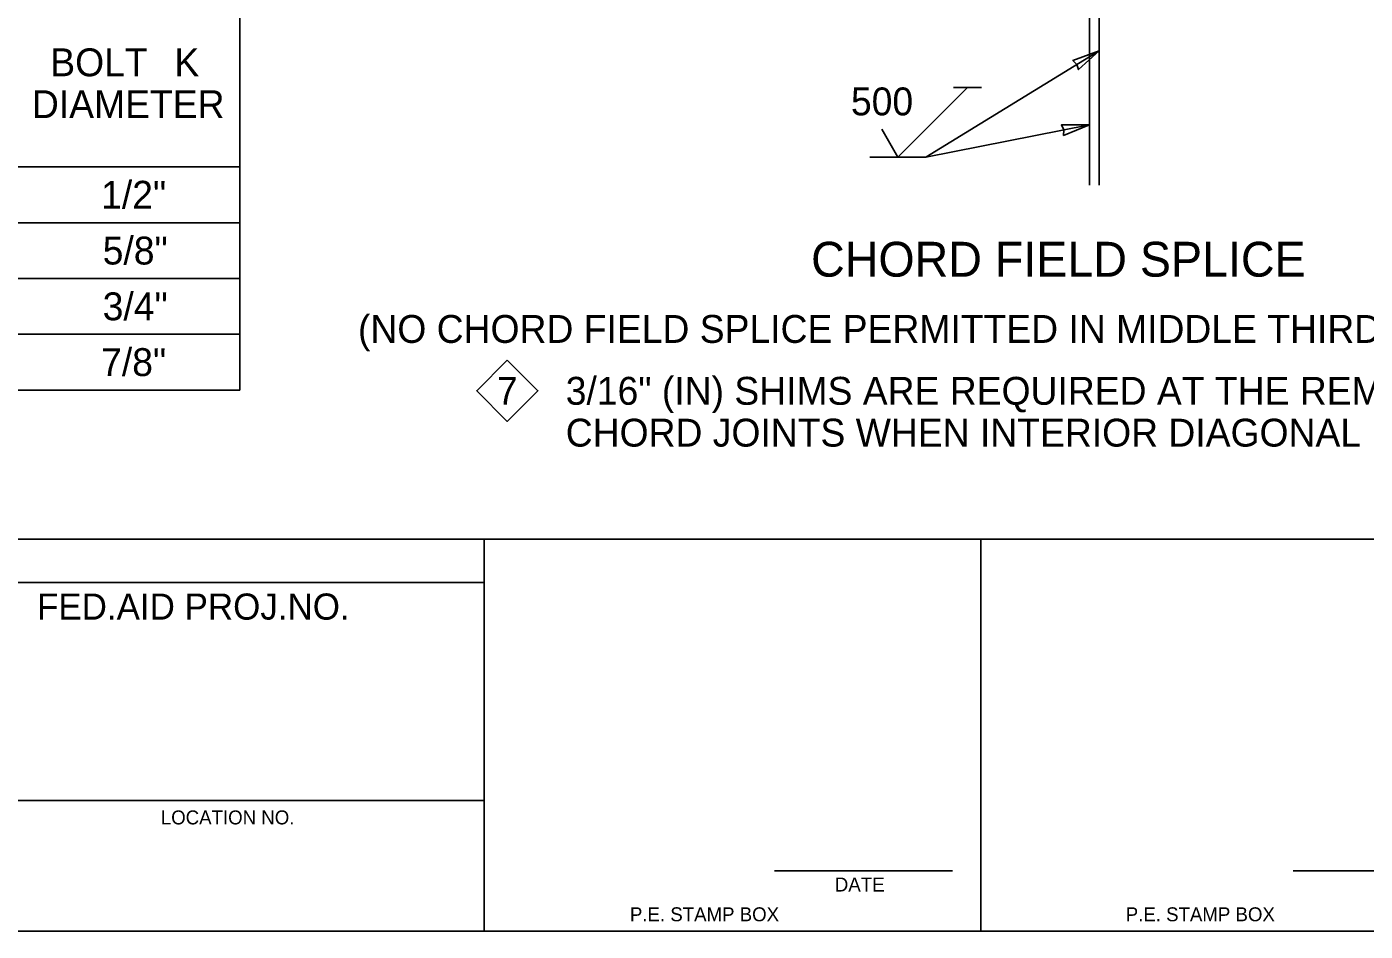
# Model space of a CAD drawing. Extents: x 99862 to 104211, y 98939 to 111076.
# Drawn here: x 101228 to 101996, y 106000 to 106519 of the extents above; entities that cross this region are included whole.
import ezdxf

# ---------------------------------------------------------------- set-up
doc = ezdxf.new("R2010")
doc.units = 0
for name, color, linetype in [('Level 15', 7, 'Continuous'), ('Level 20', 7, 'Continuous'), ('Level 40', 7, 'Continuous'), ('Level 60', 7, 'Continuous')]:
    doc.layers.add(name, color=color, linetype=linetype)

msp = doc.modelspace()

# ---------------------------------------------------------------- linework, layer by layer
at = {"layer": 'Level 15'}
for p, q in [((101837.48, 106572.6), (101837.48, 106428.1)), ((101843.1, 106572.6), (101843.1, 106428.1)), ((101743.56, 106444.1), (101843.1, 106505.18)), ((101767.56, 106484.1), (101727.56, 106444.1)), ((101759.56, 106484.1), (101775.56, 106484.1)), ((101718.32, 106460.1), (101727.56, 106444.1)), ((101837.48, 106462.65), (101743.56, 106444.1)), ((101743.56, 106444.1), (101711.56, 106444.1))]:
    msp.add_line(p, q, dxfattribs=at)
for points in [[(101843.1, 106505.18), (101831.31, 106494.32), (101830.32, 106497.33), (101828.08, 106499.58)], [(101837.48, 106462.65), (101822.65, 106456.58), (101822.76, 106459.75), (101821.45, 106462.63)]]:
    msp.add_lwpolyline(points, close=True, dxfattribs=at)
at = {"layer": 'Level 20'}
msp.add_lwpolyline([(101503.41, 106327.6), (101520.96, 106310.05), (101503.41, 106292.5), (101485.85, 106310.05)], close=True, dxfattribs=at)
at = {"layer": 'Level 40'}
for p, q in [((101349.86, 106310.52), (101349.86, 106534.52)), ((100881.41, 106438.52), (101349.86, 106438.52)), ((100881.41, 106406.52), (101349.86, 106406.52)), ((100881.41, 106374.52), (101349.86, 106374.52)), ((100881.41, 106342.52), (101349.86, 106342.52)), ((100881.41, 106310.52), (101349.86, 106310.52))]:
    msp.add_line(p, q, dxfattribs=at)
at = {"layer": 'Level 60'}
for p, q in [((100000, 106225), (103150, 106225)), ((101490.14, 106000), (101490.14, 106225)), ((101775.14, 106000), (101775.14, 106225)), ((100000, 106200), (101490.14, 106200)), ((101490.14, 106075), (101088.45, 106075)), ((101656.73, 106034.63), (101759, 106034.63)), ((101954.38, 106034.63), (102056.64, 106034.63)), ((100000, 106000), (103150, 106000))]:
    msp.add_line(p, q, dxfattribs=at)

# ---------------------------------------------------------------- texts
at = {"layer": 'Level 15'}
msp.add_text('500', height=16, dxfattribs=at).set_placement((101700.65, 106468.1))
at = {"layer": 'Level 20'}
for s, height, p in [('BOLT     ', 16, (101241.12, 106490.52)), ('K', 16, (101312.35, 106490.52)), ('DIAMETER', 16, (101230.58, 106466.52)), (' 1/2"', 16, (101264.35, 106414.52)), ('5/8"', 16, (101271.21, 106382.52)), ('CHORD FIELD SPLICE', 20, (101677.78, 106375.55)), ('3/4"', 16, (101271.21, 106350.52)), ('(NO CHORD FIELD SPLICE PERMITTED IN MIDDLE THIRD OF SPAN LENGTH)', 16, (101417.73, 106337.55)), (' 7/8"', 16, (101264.35, 106318.52)), ('7', 16, (101497.47, 106302.05)), ('3/16" (IN) SHIMS ARE REQUIRED AT THE REMAINING TWO', 16, (101536.96, 106302.05)), ('CHORD JOINTS WHEN INTERIOR DIAGONAL IS INSTALLED.', 16, (101536.96, 106278.05))]:
    msp.add_text(s, height=height, dxfattribs=at).set_placement(p)
at = {"layer": 'Level 60'}
for s, height, p in [('FED.AID PROJ.NO.', 15, (101233.51, 106178.76)), ('LOCATION NO.', 8, (101304.57, 106061.29)), ('DATE', 8.032, (101691.37, 106022.78)), ('P.E. STAMP BOX', 8, (101573.79, 106005.71)), ('P.E. STAMP BOX', 8, (101858.35, 106005.71))]:
    msp.add_text(s, height=height, dxfattribs=at).set_placement(p)

doc.saveas('drawing.dxf')
